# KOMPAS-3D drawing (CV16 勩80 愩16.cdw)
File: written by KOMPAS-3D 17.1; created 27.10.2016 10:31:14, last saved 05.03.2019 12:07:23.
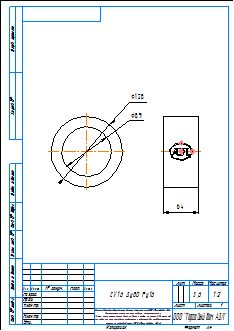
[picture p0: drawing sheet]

Sheet 1: A4, portrait

Title block, sheet 1: name: CV16 Ду80 Ру16; material: Сталь 20  ГОСТ 1050-88; mass: 3,6; sheets: 1; sheet format: A4; stored path: \\adlc.lan\data\АДЛ_ПКД\3D-модели\ADL production\Клапаны обратные ГРАНЛОК\CV16\KOMPAS 2D\CV16 Ду80 Ру16.cdw

Views: Вид 1, Проекционный вид 2
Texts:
  Klimkovich
  ADL
  Рама для чертежей
  Лит-Масса-Масштаб
  Материал-Предприятие
  Масштаб
  Изм.
  Лист
  № докум.
  Подп.
  Дата
  Лит.
  Разраб.
  Пров.
  Т.контр.
  Листов
  Внимание! Данный продукт является объектом авторского права ООО «Торговый Дом АДЛ».
  Запрещается изменение, копирование, распространение
  (в том числе путем копирования на другие сайты и ресурсы в Интернете)
  или любое иное использование информации и объектов без предварительного
  согласия правообладателя (ООО «Торговый Дом АДЛ»).
  Н.контр.
  Утв.
  ООО "Торговый дом АДЛ"
  Изменение
  Номер документа
  Подпись
  Обозначение документа
  Наименование изделия
  Масса изделия по ГОСТ 2.109-73
  Порядковый номер листа
  Общее количество листов в документе
  Характер работы, выполненной лицом, подписавшим документ
  Наименование или индекс предприятия, выпускающего документ
  Инв. № подл.
  Подп. и дата
  Взам. инв. №
  Инв. № дубл.
  Инвентарный номер подлинника по ГОСТ 2.501-68
  Подпись принявшего подлинник в отдел технической документации
  Инвентарный номер подлинника, взамен которого выпущен данный подлинник
  Инвентарный номер дубликата по ГОСТ 2.502-68
  Подпись принявшего дубликат в отдел технической документации
  Справ. №
  Перв. примен.
  Обозначение документа, взамен или на основании которого выпущен данный документ
  Обозначение документа, в котором впервые записан данный документ
  Подпись лица, копировавшего чертеж
  Обозначение формата листа
  !Рама для чертежа
Dimensions and other numbers on the sheet: 128; 89; 64; 1:2; 1; 3,6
